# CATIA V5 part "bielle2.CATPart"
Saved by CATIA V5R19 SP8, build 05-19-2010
Part number: bielle2
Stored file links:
  G:\EU_thinkMotion\CFAO_2010\MMS_groupe1\MMS_groupe1\A reprendre\OK\glenerrant\glenerrant\glenerrant\bielle2.CATPart

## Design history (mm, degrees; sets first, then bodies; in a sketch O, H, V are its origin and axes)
Set1
  Plane1: type Offset, RefPlane zx-plane, Offset 22, reversed
  Point1: (45, -23, 32)
  Point2: (0, -23, 0)
Body1 (main body)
